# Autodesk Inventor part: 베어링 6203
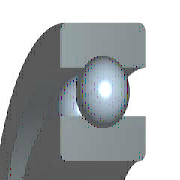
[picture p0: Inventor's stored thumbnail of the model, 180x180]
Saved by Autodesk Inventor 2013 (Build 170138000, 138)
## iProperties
IsCustomPart: 0
Created: 2014-10
Part Number: 베어링 6203
Material: 강철, 연강
Description: 깊은 그루브 볼 베어링
Document SubType Name: Modeling
Standard: KS B 2023
Designer: KYOUNG IL JANG
Standards Organization: KS
Language: ko-KR
Size Designation: 6203 - 17 x 40 x 12
Categories: <MemberInstance><Categories><Category DisplayName="샤프트 부품" InternalName="7f7aeb1f-a693-4053-b835-cee3144e0d98" Mnemonic="SHFT"><Category DisplayName="베어링" Inter
Density: 7.86 g/cm^3
Mass: 64.9809 g
Surface Area: 64.3582 cm^2
Volume: 8.26729 cm^3
Author: SeoGD™ [www.esajin.kr]
Revision Number: 1
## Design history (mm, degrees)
sketch "스케치" dims "d0" = 5.98 (= -0.26 x WD + 0.26 x BD)
  geometry: L1 (3.01, 14.25)-(8.99, 14.25); L2 (6, 14.25)-(6, 11.26); L3 (6, 14.25)-(6, 17.24); L4 (3.778, 12.249)-(0, 12.249); L5 (0, 8.5)-(12, 8.5); L6 (3.778, 16.251)-(0, 16.251); L7 (0, 20)-(12, 20); L8 (12, 8.5)-(12, 12.249); L9 (8.222, 12.249)-(12, 12.249); L10 (8.222, 16.251)-(12, 16.251); L11 (12, 20)-(12, 16.251); L12 (-1.4, 0)-(8.4, 0) reference; L13 (0, -0.3)-(0, 5.3) reference
  constraints: 22 end point, 4 point on line, 2 collinear, 2 perpendicular, 2 symmetric about line, 1 midpoint, 1 parallel, 14 other
  dimensions: "d9" = 17 diameter of L5 L12 (= WD); "d11" = 40 diameter of L7 L12 (= BD); "d12" = 12 distance between parallel lines of L8 L13 (= KB); "d13" = 24.498 diameter of L9 L12 (= 0.326 x BD + 0.674 x WD)
revolve "본체" stored, may be unused: angle "d6" = 90 deg
revolve "볼" stored, may be unused: angle "d7" = 90 deg
pattern_circular "IDS_ARRAYBALL[SIMPL:T]" dims angle "d3" = 360 deg
body "Solid1"
fillet "모깎기1" dims "d1" = 0.6 (= KRS)
other parameters: "WD" = 17 [user parameter; used in 5 equation terms], "BD" = 40 [user parameter; used in 5 equation terms], "KB" = 12 [user parameter; used in 1 equation term], "KRS" = 0.6 [user parameter; used in 1 equation term], "d4" = 0, "d5" = 0, "d8" = 0, "d14" = 0, "d15" = 0, "BBA" = 0 [user parameter], "BC0" = 4750000 [user parameter], "BC" = 9560000 [user parameter], "WR" = 8.5 (= 0.5 x WD) [user parameter]
